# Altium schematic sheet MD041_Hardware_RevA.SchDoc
size 431 x 279 mm; Date: Not shown in title block; ApprovedBy: Not shown in title block; CheckedBy: Not shown in title block; Author: Not shown in title block; CompanyName: Not shown in title block; Engineer: Not shown in title block; Organization: Not shown in title block; Address1: Not shown in title block; Address2: Not shown in title block; Address3: Not shown in title block; Address4: Not shown in title block; DocumentNumber: 3; Revision: Use project parameter SCH_Rev; SheetNumber: 4; SheetTotal: 4; PageSetup: Record=PageOptions¦CenterHorizontal=True¦CenterVertical=True¦PrintScale=1.00¦XCorrection=1.00¦YCorrection=1.00¦PrintKind=0¦BorderSize=5000000¦LeftOffset=0¦BottomOffset=0¦Orientation=2¦PaperLength=1000¦PaperWidth=1000¦Scale=100¦PaperSource=15¦PrintQuality=600¦MediaType=1¦DitherType=10¦PaperKind=Letter¦PrintScaleMode=1
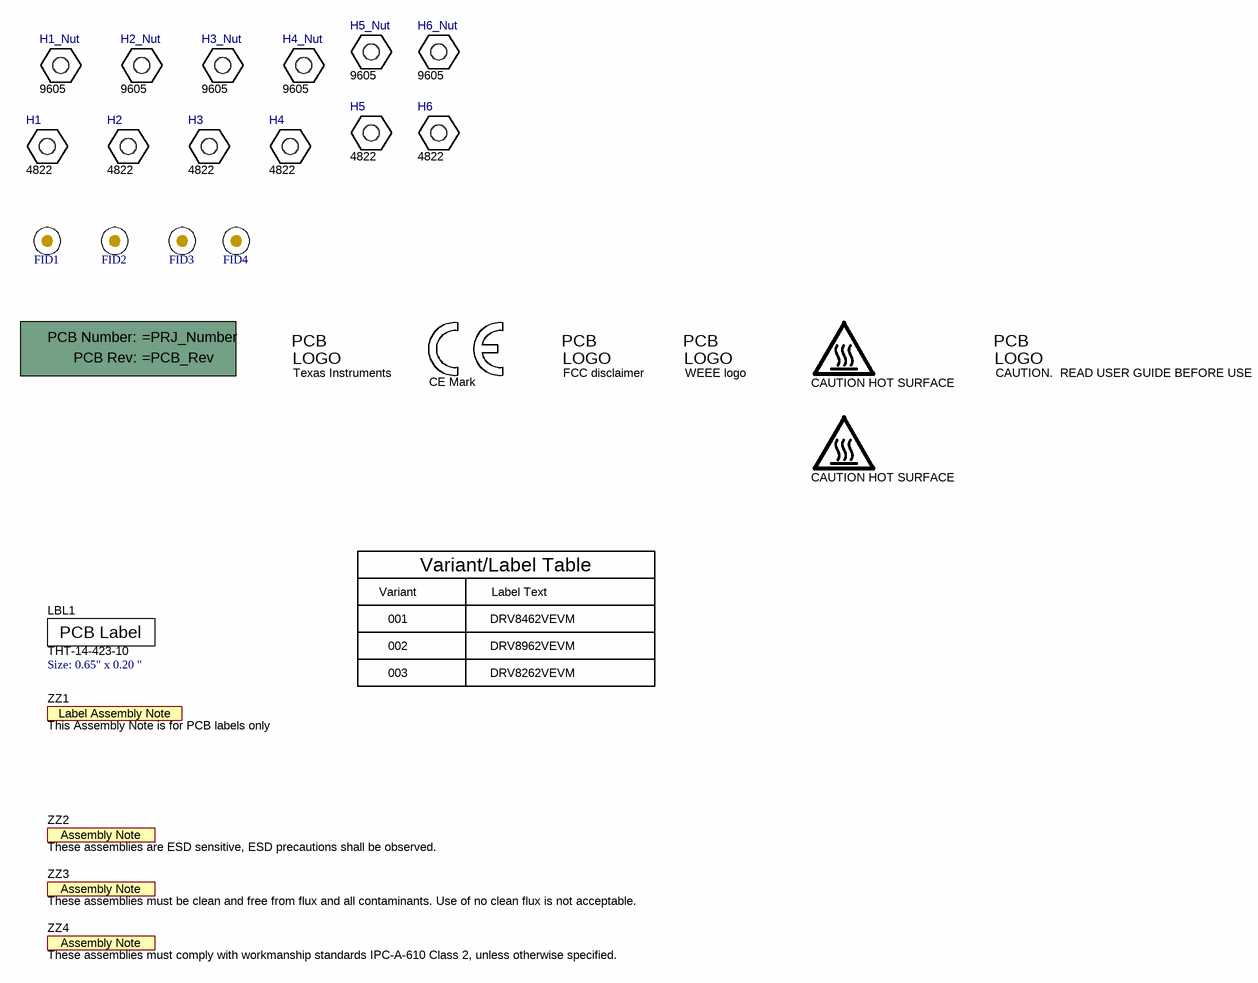
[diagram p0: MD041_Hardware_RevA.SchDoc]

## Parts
!PCB1  Printed Circuit Board  (value not drawn)  (mechanical)
FID1  Fiducial  [Fiducial10-20]  (value not drawn)
FID2  Fiducial  [Fiducial10-20]  (value not drawn)
FID3  Fiducial  [Fiducial10-20]  (value not drawn)
FID4  Fiducial  [Fiducial10-20]  (value not drawn)
H1  4822  [KEYSTONE_4822]
H1_Nut  9605  [Keystone_9605]
H2  4822  [KEYSTONE_4822]
H2_Nut  9605  [Keystone_9605]
H3  4822  [KEYSTONE_4822]
H3_Nut  9605  [Keystone_9605]
H4  4822  [KEYSTONE_4822]
H4_Nut  9605  [Keystone_9605]
H5  4822  [KEYSTONE_4822]
H5_Nut  9605  [Keystone_9605]
H6  4822  [KEYSTONE_4822]
H6_Nut  9605  [Keystone_9605]
LBL1  THT-14-423-10  Note: Size: 0.65" x 0.20 "  [Label_650x200]
LOGO1  CAUTION HOT SURFACE  [IEC_HotSurface_Small]  (no BOM)
Logo2  CE Mark  [CE_Mark_5mm]  (no BOM)
Logo3  Texas Instruments  [TI_Stacked_Overlay_Small]  (no BOM)
Logo4  FCC disclaimer  [FCC_disclaimer]  (no BOM)
Logo5  WEEE logo  [WEEE_Minimum]  (no BOM)
Logo6  CAUTION.  READ USER GUIDE BEFORE USE  [IEC_Caution_Small]  (no BOM)
LOGO7  CAUTION HOT SURFACE  [IEC_HotSurface_Small]  (no BOM)
ZZ1  This Assembly Note is for PCB labels only  [AssemblyNoteLabel]  (no BOM)
ZZ2  These assemblies are ESD sensitive, ESD precautions shall be observed.  [AssemblyNote]  (no BOM)
ZZ3  These assemblies must be clean and free from flux and all contaminants. Use of no clean flux is not acceptable.  [AssemblyNote]  (no BOM)
ZZ4  These assemblies must comply with workmanship standards IPC-A-610 Class 2, unless otherwise specified.  [AssemblyNote]  (no BOM)

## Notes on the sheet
- Variant
- Variant/Label Table
- Label Text
- 001
- 002
- DRV8462VEVM
- DRV8962VEVM
- 003
- DRV8262VEVM

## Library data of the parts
!PCB1 = CMP-0003618-2: Manufacturer: Any
FID1-FID4 = CMP-0077181-1: Fiducial mark.  There is nothing to buy or mount.
H1-H6 = CMP-0003678-1: Standoff, Hex, 1.25"L #6-32 Nylon; Manufacturer: Keystone
H1_Nut H2_Nut H3_Nut H4_Nut H5_Nut H6_Nut = CMP-0003948-1: Small nylon hex nut, 0.10 thick with a 0.250 outside diameter and a 4-40 threading; Manufacturer: Keystone; CompType: Standoff
LBL1 = CMP-0003625-1: Thermal Transfer Printable Labels, 0.650" W x 0.200" H - 10,000 per roll; Manufacturer: Brady
LOGO1 LOGO7 = CMP-0074837-2: IEC 61010-1 Hot Surface Warning; Manufacturer: Texas Instruments; SymbolCreator: a0412235; CompType: IC; AEC Category: Q200
Logo2 = CMP-0074844-1: SymbolCreator: a0412235
Logo3 = CMP-0074838-1: Texas Instrument Corporate Signature; SymbolCreator: a0412235; Lib Reference: TI_Logo
Logo4 = CMP-0074847-1: FCC_disclaimer
Logo5 = CMP-0074769-3: Manufacturer: Texas Instruments; CompType: IC; AEC Category: Q200
Logo6 = CMP-0074836-1: IEC 61010-1 Caution Warning; SymbolCreator: a0412235; Lib Reference: IEC_Caution
ZZ1 = CMP-0003616-3
ZZ2 = CMP-0077236-1
ZZ3 = CMP-0077237-1
ZZ4 = CMP-0077238-1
